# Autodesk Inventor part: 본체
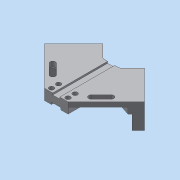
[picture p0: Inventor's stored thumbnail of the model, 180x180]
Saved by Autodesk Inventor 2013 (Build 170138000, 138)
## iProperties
Created: 2019-04
Part Number: 본체
Material: 알루미늄 6061
Document SubType Name: Modeling
Designer: dgall
Density: 1 g/cm^3
Author: dgall
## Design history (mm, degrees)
sketch "스케치1"
  geometry: L1 (0, 84.853)-(0, -84.853); L2 (-84.853, 0)-(-35.355, 49.497); L3 (0, 84.853)-(-35.355, 49.497); L4 (84.853, 0)-(35.355, 49.497); L5 (35.355, 49.497)-(0, 84.853); L6 (-20, -64.853)-(20, -64.853); L7 (84.853, 0)-(20, -64.853); L8 (-20, -64.853)-(-84.853, 0); L9 (0, -84.853)-(-20, -64.853); L10 (0, -84.853)-(20, -64.853); L11 (-35.355, 49.497)-(-14.005, 28.147); L12 (-14.005, 28.147)-(14.005, 28.147); L13 (14.005, 28.147)-(35.355, 49.497); L14 (-74.246, -10.607)-(-24.749, 38.891); L15 (24.749, 38.891)-(74.246, -10.607); L16 (-70.711, -14.142)-(-49.497, -7.071); L17 (-49.497, -7.071)-(-20, -36.569); L18 (-20, -36.569)-(-20, -64.853); L19 (70.711, -14.142)-(49.497, -7.071); L20 (49.497, -7.071)-(20, -36.569); L21 (20, -36.569)-(20, -64.853); L22 (-52.679, -24.395)-(-35.709, -41.366); L23 (-46.315, -18.031)-(-29.345, -35.002); L24 (46.315, -18.031)-(29.345, -35.002); L25 (35.709, -41.366)-(52.679, -24.395); L26 (-8, 28.147)-(-8, -64.853); L27 (8, 28.147)-(8, -64.853); A1 r 4.5 centre (-49.497, -21.213) between (-46.315, -18.031) and (-52.679, -24.395); A2 r 4.5 centre (-32.527, -38.184) between (-35.709, -41.366) and (-29.345, -35.002); A3 r 4.5 centre (49.497, -21.213) between (52.679, -24.395) and (46.315, -18.031); A4 r 4.5 centre (32.527, -38.184) between (29.345, -35.002) and (35.709, -41.366); 2 further points
  constraints: 56 end point, 13 perpendicular, 10 point on line, 8 point on circle, 5 parallel, 4 centre point, 4 tangent, 3 collinear, 3 equal radius, 2 vertical, 1 coincident, 1 midpoint
  dimensions: "d0" = 120 distance of L4.start L1.start; "d3" = 70 distance of L2.start L2.end; "d4" = 70 distance of L4.start L4.end; "d5" = 40 distance of L6.start L6.end; "d6" = 93 distance between parallel lines of L6 L12; "d7" = 15 distance between parallel lines of L2 L14; "d8" = 15 distance between parallel lines of L4 L15; "d9" = 20 distance of L2.start L16.start; "d10" = 20 distance between parallel lines of L8 L17; "d11" = 30 distance from line of L2 L16.end; "d12" = 20 distance between parallel lines of L7 L20; "d13" = 20 distance of L4.start L19.start; "d14" = 30 distance from line of L19.end L4; "d15" = 9 diameter of A1; "d16" = 24 distance of A2.centre A1.centre; "d17" = 40 distance from line of L2 A1.centre; "d18" = 10 distance from line of L8 A1.centre; "d19" = 10 distance from line of L8 A2.centre; "d20" = 24 distance of A4.centre A3.centre; "d21" = 40 distance from line of L4 A3.centre; "d22" = 10 distance from line of L7 A3.centre; "d23" = 10 distance from line of L7 A4.centre; "d24" = 16 distance between parallel lines of L27 L26; "d25" = 8 distance between parallel lines of L26 L1
extrude "돌출1" new body sketch "스케치1" distance "d26" = 8; taper "d27" = 0 deg
extrude "돌출2" join sketch "스케치1" distance "d28" = 18; taper "d29" = 0 deg
extrude "돌출3" join sketch "스케치1" distance "d30" = 42; taper "d31" = 0 deg
extrude "돌출4" join sketch "스케치1" distance "d32" = 18; taper "d33" = 0 deg
sketch "스케치2"
  geometry: L1 (-20, -64.853)-(20, -64.853) reference; L2 (14.005, 28.147)-(-14.005, 28.147) reference; L3 (-6, 28.147)-(-6, -64.853); L4 (6, 28.147)-(6, -64.853); 1 further point
  constraints: 4 end point, 4 point on line, 2 perpendicular
  dimensions: "d34" = 12 distance between parallel lines of L4 L3; "d35" = 6 distance from line of L3 point (0, 0)
extrude "돌출5" cut sketch "스케치2" distance "d36" = 3; taper "d37" = 0 deg
sketch "스케치3"
  geometry: L1 (-20, -64.853)-(20, -64.853) reference; L2 (14.005, 28.147)-(-14.005, 28.147) reference; L3 (-8, 28.147)-(-8, -64.853); L4 (8, 28.147)-(8, -64.853); 1 further point
  constraints: 4 end point, 4 point on line, 2 perpendicular
  dimensions: "d38" = 16 distance between parallel lines of L4 L3; "d39" = 8 distance from line of L3 point (0, 0)
extrude "돌출6" cut sketch "스케치3" distance "d40" = 3.5; taper "d41" = 0 deg
sketch "스케치5"
  geometry: L1 (6, 28.147)-(6, -64.853) reference; L2 (6, -64.853)-(20, -64.853) reference; L3 (6, -64.853)-(-6, -64.853) reference; L4 (0, -64.853)-(0, 0); L5 (-35.709, -41.366)-(-52.679, -24.395) reference; L6 (-46.315, -18.031)-(-29.345, -35.002) reference; L7 (-6, -64.853)-(-6, 28.147) reference; L8 (-6, 28.147)-(-14.005, 28.147) reference; L9 (-14.005, 28.147)-(-35.355, 49.497) reference; L10 (-35.355, 49.497)-(-84.853, 0) reference; L11 (-84.853, 0)-(-20, -64.853) reference; L12 (-20, -64.853)-(-6, -64.853) reference; A1 r 4.5 centre (-49.497, -21.213) between (-46.315, -18.031) and (-52.679, -24.395) reference; A2 r 4.5 centre (-32.527, -38.184) between (-35.709, -41.366) and (-29.345, -35.002) reference; 4 further points
  constraints: 2 end point, 2 horizontal alignment, 2 vertical alignment, 1 midpoint, 1 parallel
  dimensions: "d47" = 12 distance of point (14, -46.853) point (14, -58.853); "d49" = 6 distance from line of L2 point (14, -58.853); "d50" = 28 distance of point (-14, -58.853) point (14, -58.853); "d51" = 14 distance from line of point (14, -58.853) L4
hole "구멍1" sketch "스케치5" at (-14, -46.853), (14, -46.853), (14, -58.853), (-14, -58.853) diameter "d52" = 4.5; stored, may be unused: countersink angle "d56" = 90 deg, drill point angle "d58" = 118 deg; dims "d53" = 6, "d54" = 8, "d55" = 10, "d57" = 8
fillet "모깎기1" dims "d59" = 5
fillet "모깎기2" dims "d60" = 5
sketch "스케치7"
  geometry: L1 (-74.246, -10.607)-(-24.749, 38.891) reference; L2 (-24.749, 38.891)-(-35.355, 49.497) reference; 2 further points
  constraints: 1 other
  dimensions: "d63" = 35 distance from line of L2 point (-54.801, 19.445); "d64" = 7.5 distance from line of L1 point (-54.801, 19.445)
feature "엠보싱1" sketch "스케치7" dims "d65" = 0.5, "d66" = 0
node "솔리드1"
node "투영된 루프1"
